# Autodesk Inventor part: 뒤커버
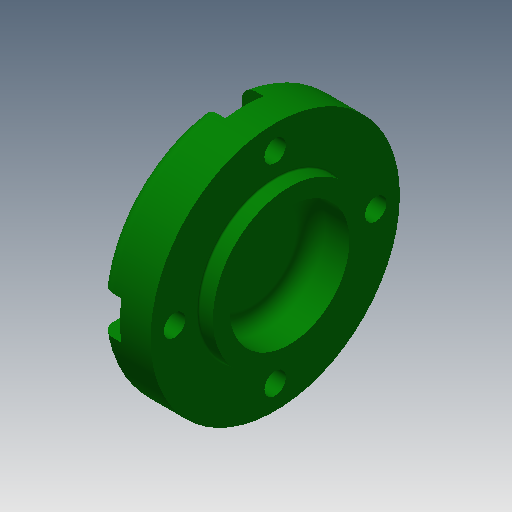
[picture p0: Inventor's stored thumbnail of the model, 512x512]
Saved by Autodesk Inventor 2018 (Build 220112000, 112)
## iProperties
Created: 2015-11
Part Number: 뒤커버
Material: 알루미늄 6061
Document SubType Name: Modeling
Designer: mduedu
Density: 1 g/cm^3
Appearance: 진녹색
Author: mduedu
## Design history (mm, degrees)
sketch "스케치1"
  geometry: L1 (-7, 0)-(7, 0); L2 (-7, 0)-(-7, 26); L3 (-7, 26)-(4, 26); L4 (4, 26)-(4, 16); L5 (4, 16)-(7, 16); L6 (7, 16)-(7, 0); 2 further points
  constraints: 12 end point, 3 perpendicular, 2 parallel, 1 coincident, 1 horizontal, 1 midpoint
  dimensions: "d0" = 14 distance of L1.start L1.end; "d1" = 52 diameter of L3 L1; "d2" = 3 distance of L4.end L5.end; "d3" = 32 diameter of L5 L1
revolve "회전1" sketch "스케치1" stored, may be unused: angle "d4" = 90 deg
hole "구멍1" diameter "d7" = 25; stored, may be unused: countersink angle "d11" = 90 deg, drill point angle "d13" = 0 deg; dims "d8" = 6, "d9" = 4, "d10" = 2, "d12" = 8, "d62" = 10, "d63" = 10
fillet "모깎기2" dims "d36" = 3
fillet "모깎기3" dims "d37" = 3
fillet "모깎기4" dims "d38" = 0.3
sketch "스케치3" dims "d61" = 42
  geometry: C1 r 26 at (0, 0) reference; 2 further points
  constraints: 2 vertical alignment, 1 coincident, 2 other
hole "구멍4" sketch "스케치3" at (0, -21) diameter "d44" = 4.5; stored, may be unused: countersink angle "d48" = 90 deg, drill point angle "d50" = 0 deg; dims "d45" = 6, "d46" = 8, "d47" = 4.6, "d49" = 8
sketch "스케치4"
  geometry: L1 (-4, 0)-(-4, -4.69); L2 (4, 0)-(4, -4.69); A1 r 4 centre (0, 0) between (3.614, -1.714) and (-3.614, -1.714) reference; A2 r 26 centre (0, 21) between (-4, -4.69) and (4, -4.69) reference; 1 further point
  constraints: 4 end point, 4 point on circle, 2 tangent, 1 parallel, 1 vertical
extrude "돌출1" cut sketch "스케치4" extent not by distance; stored distance "d51" = 0; taper "d52" = 0 deg
node "솔리드1"
pattern_circular "원형 패턴1" dims angle "d54" = 360 deg
